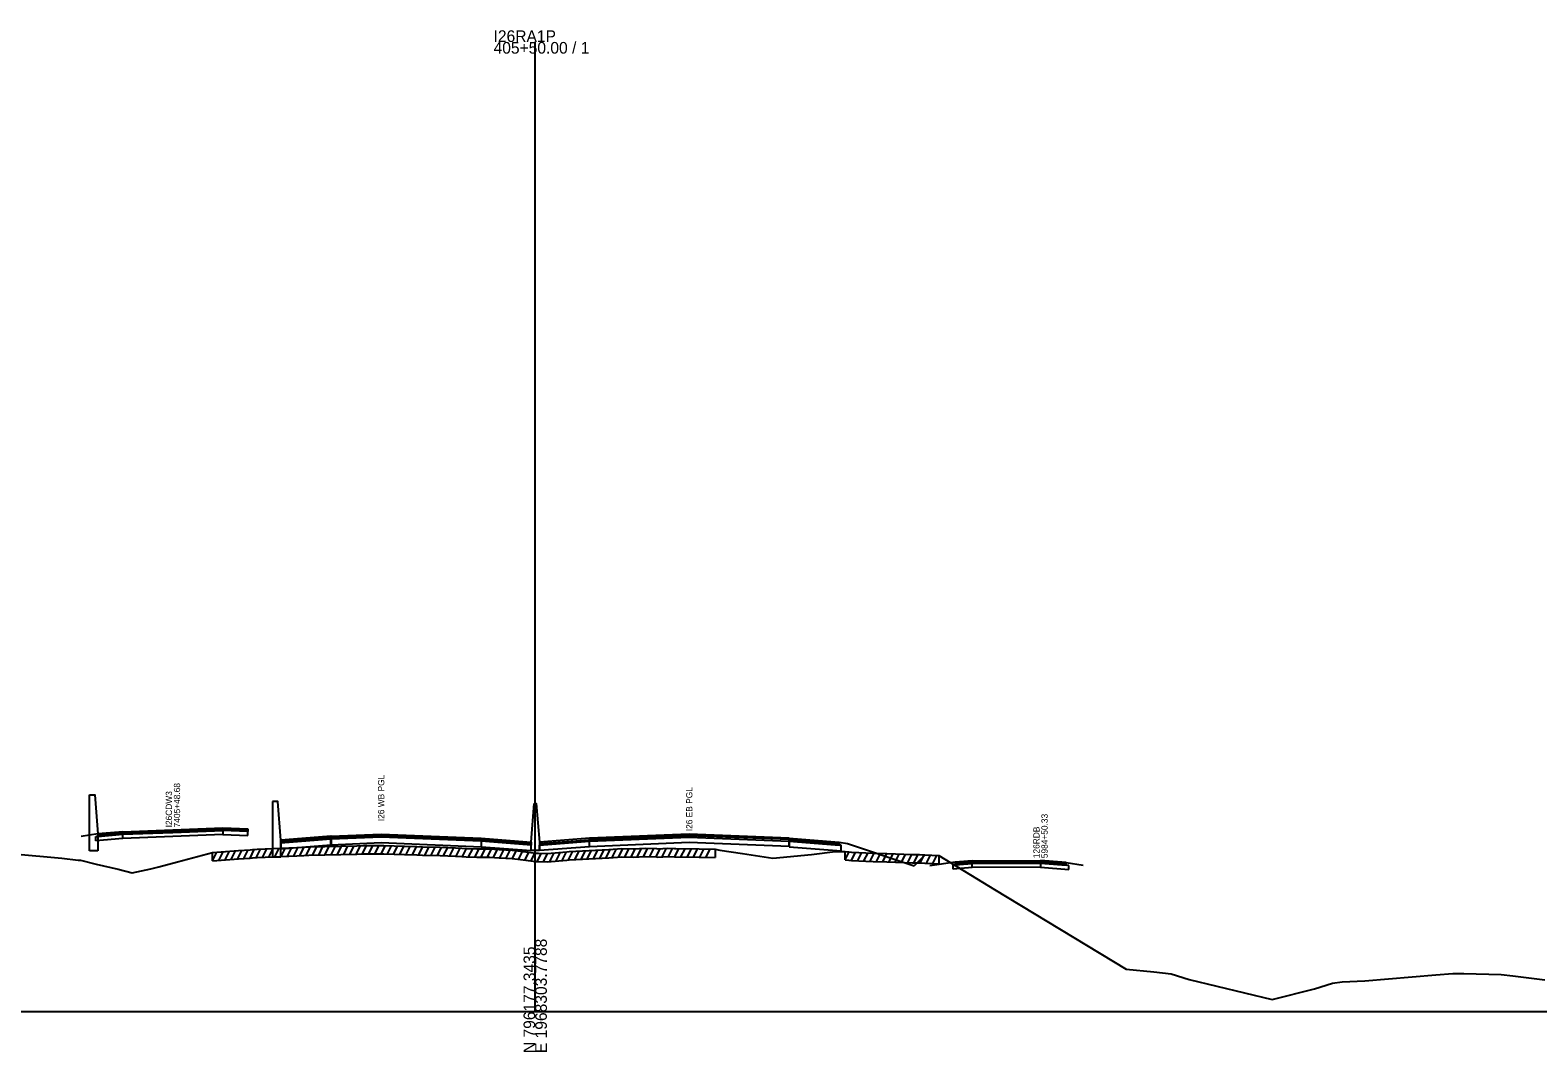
# Model space of a CAD drawing. Extents: x 1017 to 19997, y -1947 to 50737.
# Drawn here: x 16478.7 to 16840.8, y 5490.3 to 5735.7 of the extents above; entities that cross this region are included whole.
import ezdxf

# ---------------------------------------------------------------- set-up
doc = ezdxf.new("R2010")
doc.units = 0
for name, color, linetype in [('RD_GPK_XS_Cell', 7, 'Continuous'), ('RD_XS_Base', 7, 'Continuous'), ('RD_XS_ExGround', 7, 'Continuous'), ('RD_XS_ExPaveRet', 7, 'Continuous'), ('RD_XS_Greenside', 7, 'Continuous'), ('RD_XS_MedBWall', 7, 'Continuous'), ('RD_XS_Pave', 7, 'Continuous'), ('RD_XS_PaveOvlay', 7, 'Continuous'), ('RD_XS_TieSlope', 7, 'Continuous'), ('RD_XS_TX_Notes', 7, 'Continuous')]:
    doc.layers.add(name, color=color, linetype=linetype)

msp = doc.modelspace()

# ---------------------------------------------------------------- linework, layer by layer
at = {"layer": 'RD_GPK_XS_Cell'}
for p, q in [((16600, 5500), (16600, 5732.84)), ((16000, 5500), (16600, 5500)), ((16600, 5500), (17200, 5500))]:
    msp.add_line(p, q, dxfattribs=at)
at = {"layer": 'RD_XS_Base'}
for points in [[(16525, 5543.5), (16525, 5542.5)], [(16531, 5542.25), (16531, 5543.25)], [(16494.5, 5542.02), (16495, 5542.06), (16501, 5542.55)], [(16494.5, 5541.02), (16494.5, 5542.02)], [(16501, 5541.55), (16494.5, 5541.02)], [(16501, 5541.55), (16501, 5542.55)], [(16525, 5542.5), (16513, 5542.02), (16501, 5541.55)], [(16525, 5542.5), (16531, 5542.25)], [(16550.95, 5541.4), (16538.95, 5540.44)], [(16538.95, 5540.44), (16538.95, 5539.1)], [(16538.95, 5539.1), (16550.95, 5540.06)], [(16550.95, 5540.06), (16550.95, 5541.4)], [(16551, 5540.06), (16550.95, 5540.06)], [(16551, 5541.4), (16551, 5540.06)], [(16551, 5540.06), (16563, 5540.55), (16587, 5539.58)], [(16599, 5539.98), (16587, 5540.92)], [(16587, 5540.92), (16587, 5539.58)], [(16587, 5539.58), (16599, 5538.64)], [(16599, 5538.64), (16599, 5539.98)], [(16601, 5538.64), (16601, 5539.98)], [(16613, 5539.58), (16601, 5538.64)], [(16613, 5539.58), (16613, 5540.92)], [(16660.95, 5539.59), (16637, 5540.55), (16613, 5539.58)], [(16660.95, 5539.59), (16660.95, 5540.93)], [(16661, 5539.58), (16660.95, 5539.59)], [(16661, 5540.92), (16661, 5539.58)], [(16673.5, 5539.93), (16673, 5539.97), (16661, 5540.92)], [(16661, 5539.58), (16673.5, 5538.59)], [(16673.5, 5538.59), (16673.5, 5539.93)], [(16700.37, 5535.21), (16700.89, 5535.25), (16704.97, 5535.56)], [(16700.37, 5534.21), (16700.37, 5535.21)], [(16704.97, 5534.56), (16700.37, 5534.21)], [(16704.97, 5534.56), (16704.97, 5535.56)], [(16721.33, 5534.63), (16704.97, 5534.56)], [(16721.33, 5535.63), (16721.33, 5534.63)], [(16728.18, 5535.08), (16727.47, 5535.14), (16721.33, 5535.63)], [(16721.33, 5534.63), (16728.18, 5534.08)], [(16728.18, 5534.08), (16728.18, 5535.08)]]:
    msp.add_lwpolyline(points, dxfattribs=at)
at = {"layer": 'RD_XS_ExGround'}
msp.add_lwpolyline([(16474.76, 5537.9), (16486.29, 5536.81), (16490.21, 5536.38), (16490.77, 5536.31), (16494.57, 5535.38), (16499.84, 5534.15), (16503.21, 5533.29), (16507.73, 5534.28), (16509.62, 5534.78), (16514.11, 5535.98), (16522.51, 5538.2), (16528.71, 5538.63), (16531.56, 5538.83), (16532.09, 5538.87), (16533.21, 5538.95), (16542.75, 5539.41), (16544.4, 5539.5), (16545.62, 5539.52), (16557.16, 5539.81), (16558.77, 5539.83), (16563.64, 5539.88), (16568.64, 5539.69), (16571.59, 5539.59), (16572.91, 5539.56), (16577.21, 5539.48), (16580.84, 5539.3), (16582.4, 5539.22), (16583.39, 5539.16), (16585.96, 5539.03), (16588.77, 5539.08), (16589.09, 5539.08), (16591.31, 5538.93), (16594.48, 5538.72), (16597.12, 5538.39), (16600.12, 5538.01), (16600.76, 5538), (16602.88, 5537.98), (16607.63, 5538.37), (16608.15, 5538.42), (16617.7, 5538.92), (16620.84, 5539.11), (16623.49, 5539.05), (16626.49, 5539.24), (16629.11, 5539.12), (16629.46, 5539.1), (16631.87, 5539.21), (16633.47, 5539.15), (16633.81, 5539.14), (16639.37, 5539.03), (16643.19, 5538.96), (16644.34, 5538.78), (16649.77, 5537.95), (16657.05, 5536.86), (16666.36, 5537.73), (16672.06, 5538.42), (16673.77, 5538.41), (16674.45, 5538.4), (16675.32, 5538.34), (16675.96, 5538.3), (16681.16, 5538.06), (16684.43, 5537.92), (16690.62, 5537.72), (16691.05, 5537.71), (16692.32, 5537.67), (16693.53, 5537.61), (16696.91, 5537.45), (16710.3, 5529.33), (16741.94, 5510.2), (16748.59, 5509.52), (16752.75, 5509.08), (16757.08, 5507.7), (16777.01, 5502.9), (16787.12, 5505.44), (16791.44, 5506.81), (16793.78, 5507.09), (16799.21, 5507.36), (16816.3, 5508.78), (16820.36, 5509.14), (16822.97, 5509.11), (16832, 5508.87), (16834.77, 5508.58), (16842.45, 5507.63)], dxfattribs=at)
at = {"layer": 'RD_XS_ExPaveRet'}
for p, q in [((16546.51, 5537.54), (16547.52, 5539.57)), ((16548.01, 5537.58), (16549.02, 5539.61)), ((16549.51, 5537.62), (16550.52, 5539.64)), ((16551.01, 5537.66), (16552.02, 5539.68)), ((16552.51, 5537.69), (16553.52, 5539.72)), ((16554.01, 5537.73), (16555.02, 5539.75)), ((16555.51, 5537.77), (16556.52, 5539.79)), ((16557.01, 5537.8), (16558.02, 5539.82)), ((16558.51, 5537.83), (16559.52, 5539.84)), ((16560.01, 5537.84), (16561.02, 5539.86)), ((16561.51, 5537.86), (16562.52, 5539.87)), ((16563.01, 5537.88), (16564.01, 5539.87)), ((16564.51, 5537.85), (16565.49, 5539.81)), ((16566.01, 5537.79), (16566.99, 5539.76)), ((16567.51, 5537.74), (16568.49, 5539.7)), ((16569.01, 5537.68), (16569.99, 5539.65)), ((16570.51, 5537.63), (16571.49, 5539.6)), ((16572.01, 5537.58), (16573, 5539.55)), ((16522.51, 5536.2), (16523.55, 5538.27)), ((16522.51, 5536.2), (16522.51, 5538.2)), ((16522.51, 5536.2), (16528.71, 5536.63)), ((16524.01, 5536.3), (16525.05, 5538.37)), ((16525.51, 5536.41), (16526.55, 5538.48)), ((16527.01, 5536.51), (16528.05, 5538.58)), ((16528.51, 5536.62), (16529.55, 5538.69)), ((16528.71, 5536.63), (16531.56, 5536.83)), ((16530.01, 5536.72), (16531.05, 5538.79)), ((16531.51, 5536.82), (16532.55, 5538.9)), ((16531.56, 5536.83), (16532.09, 5536.87)), ((16532.09, 5536.87), (16533.21, 5536.95)), ((16533.01, 5536.94), (16534.04, 5538.99)), ((16533.21, 5536.95), (16542.75, 5537.41)), ((16534.51, 5537.02), (16535.54, 5539.07)), ((16536.01, 5537.09), (16537.04, 5539.14)), ((16537.51, 5537.16), (16538.54, 5539.21)), ((16539.01, 5537.23), (16540.04, 5539.28)), ((16540.51, 5537.31), (16541.54, 5539.36)), ((16542.01, 5537.38), (16543.04, 5539.43)), ((16542.75, 5537.41), (16544.4, 5537.5)), ((16543.51, 5537.45), (16544.54, 5539.5)), ((16544.4, 5537.5), (16545.62, 5537.52)), ((16545.01, 5537.51), (16546.02, 5539.53)), ((16545.62, 5537.52), (16557.16, 5537.81)), ((16557.16, 5537.81), (16558.77, 5537.83)), ((16558.77, 5537.83), (16563.64, 5537.88)), ((16563.64, 5537.88), (16568.64, 5537.69)), ((16568.64, 5537.69), (16571.59, 5537.59)), ((16571.59, 5537.59), (16572.91, 5537.56)), ((16572.91, 5537.56), (16577.21, 5537.48)), ((16573.51, 5537.54), (16574.5, 5539.53)), ((16575.01, 5537.52), (16576, 5539.5)), ((16576.51, 5537.49), (16577.5, 5539.46)), ((16577.21, 5537.48), (16580.84, 5537.3)), ((16578.01, 5537.44), (16578.99, 5539.39)), ((16579.51, 5537.36), (16580.49, 5539.31)), ((16580.84, 5537.3), (16582.4, 5537.22)), ((16581.01, 5537.29), (16581.99, 5539.24)), ((16582.4, 5537.22), (16583.39, 5537.16)), ((16582.51, 5537.21), (16583.48, 5539.15)), ((16583.39, 5537.16), (16585.96, 5537.03)), ((16584.01, 5537.13), (16584.99, 5539.08)), ((16585.51, 5537.05), (16586.51, 5539.04)), ((16585.96, 5537.03), (16588.77, 5537.08)), ((16587.01, 5537.05), (16588.02, 5539.07)), ((16588.51, 5537.08), (16589.5, 5539.05)), ((16588.77, 5537.08), (16589.09, 5537.08)), ((16589.09, 5537.08), (16591.31, 5536.93)), ((16590.01, 5537.02), (16590.98, 5538.96)), ((16591.31, 5536.93), (16594.48, 5536.72)), ((16591.51, 5536.92), (16592.48, 5538.85)), ((16593.01, 5536.82), (16593.98, 5538.75)), ((16594.48, 5536.72), (16597.12, 5536.39)), ((16594.51, 5536.71), (16595.45, 5538.6)), ((16596.01, 5536.53), (16596.95, 5538.41)), ((16597.12, 5536.39), (16600.12, 5536.01)), ((16597.51, 5536.34), (16598.45, 5538.22)), ((16599.01, 5536.15), (16599.95, 5538.04)), ((16600.12, 5536.01), (16600.76, 5536)), ((16600.51, 5536.01), (16601.51, 5538)), ((16600.76, 5536), (16602.88, 5535.98)), ((16602.01, 5535.99), (16603.01, 5537.99)), ((16602.88, 5535.98), (16607.63, 5536.37)), ((16603.51, 5536.03), (16604.55, 5538.12)), ((16605.01, 5536.16), (16606.05, 5538.24)), ((16606.51, 5536.28), (16607.55, 5538.37)), ((16607.63, 5536.37), (16608.15, 5536.42)), ((16608.01, 5536.41), (16609.04, 5538.47)), ((16608.15, 5536.42), (16617.7, 5536.92)), ((16609.51, 5536.49), (16610.54, 5538.54)), ((16611.01, 5536.57), (16612.04, 5538.62)), ((16612.51, 5536.65), (16613.54, 5538.7)), ((16614.01, 5536.73), (16615.04, 5538.78)), ((16615.51, 5536.81), (16616.54, 5538.86)), ((16617.01, 5536.88), (16618.04, 5538.94)), ((16617.7, 5536.92), (16620.84, 5537.11)), ((16618.51, 5536.97), (16619.54, 5539.03)), ((16620.01, 5537.06), (16621.03, 5539.1)), ((16620.84, 5537.11), (16623.49, 5537.05)), ((16621.51, 5537.09), (16622.5, 5539.07)), ((16623.01, 5537.06), (16624.02, 5539.09)), ((16623.49, 5537.05), (16626.49, 5537.24)), ((16624.51, 5537.12), (16625.55, 5539.18)), ((16626.01, 5537.21), (16627.01, 5539.22)), ((16626.49, 5537.24), (16629.11, 5537.12)), ((16627.51, 5537.2), (16628.49, 5539.15)), ((16629.01, 5537.12), (16630.01, 5539.13)), ((16629.11, 5537.12), (16629.46, 5537.1)), ((16629.46, 5537.1), (16631.87, 5537.21)), ((16630.51, 5537.15), (16631.53, 5539.19)), ((16631.87, 5537.21), (16633.47, 5537.15)), ((16632.01, 5537.2), (16633, 5539.17)), ((16633.47, 5537.15), (16633.81, 5537.14)), ((16633.51, 5537.15), (16634.5, 5539.13)), ((16633.81, 5537.14), (16639.37, 5537.03)), ((16635.01, 5537.12), (16636, 5539.1)), ((16636.51, 5537.09), (16637.5, 5539.07)), ((16638.01, 5537.06), (16639, 5539.04)), ((16639.37, 5537.03), (16643.19, 5536.96)), ((16639.51, 5537.03), (16640.5, 5539.01)), ((16641.01, 5537), (16642, 5538.98)), ((16643.19, 5538.96), (16643.19, 5536.96)), ((16674.45, 5536.4), (16674.45, 5538.4)), ((16674.45, 5536.4), (16675.42, 5538.34)), ((16674.45, 5536.4), (16675.32, 5536.34)), ((16675.32, 5536.34), (16675.96, 5536.3)), ((16675.95, 5536.3), (16676.93, 5538.26)), ((16675.96, 5536.3), (16681.16, 5536.06)), ((16677.45, 5536.23), (16678.43, 5538.19)), ((16678.95, 5536.16), (16679.93, 5538.12)), ((16680.45, 5536.1), (16681.43, 5538.05)), ((16681.16, 5536.06), (16684.43, 5535.92)), ((16681.95, 5536.03), (16682.93, 5537.98)), ((16683.45, 5535.96), (16684.43, 5537.92)), ((16684.95, 5535.9), (16685.93, 5537.87)), ((16686.45, 5535.85), (16687.43, 5537.82)), ((16687.95, 5535.8), (16688.93, 5537.77)), ((16689.45, 5535.76), (16690.43, 5537.73)), ((16690.95, 5535.71), (16691.93, 5537.68)), ((16692.45, 5535.66), (16693.43, 5537.62)), ((16693.95, 5535.59), (16694.93, 5537.55)), ((16695.45, 5535.52), (16696.43, 5537.47)), ((16696.91, 5537.45), (16696.91, 5535.45)), ((16684.43, 5535.92), (16690.62, 5535.72)), ((16690.62, 5535.72), (16691.05, 5535.71)), ((16691.05, 5535.71), (16692.32, 5535.67)), ((16692.32, 5535.67), (16693.53, 5535.61)), ((16693.53, 5535.61), (16696.91, 5535.45))]:
    msp.add_line(p, q, dxfattribs=at)
at = {"layer": 'RD_XS_Greenside'}
for points in [[(16495, 5542.7), (16491, 5542.06)], [(16673, 5540.64), (16675, 5540.31)], [(16675, 5540.31), (16691, 5534.97)], [(16700.89, 5535.88), (16694.75, 5534.95)], [(16727.47, 5535.77), (16731.56, 5535.13)]]:
    msp.add_lwpolyline(points, dxfattribs=at)
at = {"layer": 'RD_XS_MedBWall'}
for points in [[(16493, 5538.56), (16493, 5552.04)], [(16493, 5552.04), (16494.25, 5552.04), (16495, 5542.7)], [(16538.95, 5541.12), (16538.2, 5550.46), (16536.95, 5550.46)], [(16536.95, 5550.46), (16536.95, 5537.12)], [(16599, 5540.64), (16599.75, 5549.98)], [(16599.75, 5549.98), (16600.25, 5549.98), (16601, 5540.64)], [(16495, 5542.7), (16495, 5538.56)], [(16538.95, 5537.12), (16538.95, 5541.12)], [(16599, 5538.64), (16599, 5539.98), (16599, 5540.64)], [(16601, 5540.64), (16601, 5539.98), (16601, 5538.64)], [(16495, 5538.56), (16493, 5538.56)], [(16536.95, 5537.12), (16538.95, 5537.12)], [(16601, 5538.64), (16599, 5538.64)]]:
    msp.add_lwpolyline(points, dxfattribs=at)
at = {"layer": 'RD_XS_Pave'}
for points in [[(16525, 5543.82), (16513, 5543.34), (16501, 5542.86)], [(16501, 5542.55), (16513, 5543.02), (16525, 5543.5)], [(16525, 5543.5), (16525, 5543.82)], [(16525, 5543.82), (16531, 5543.58)], [(16531, 5543.25), (16525, 5543.5)], [(16531, 5543.58), (16531, 5543.25)], [(16495, 5542.38), (16501, 5542.86)], [(16501, 5542.55), (16495, 5542.06)], [(16495, 5542.06), (16495, 5542.38)], [(16501, 5542.86), (16501, 5542.55)], [(16550.95, 5541.74), (16538.95, 5540.78)], [(16538.95, 5540.78), (16538.95, 5540.44)], [(16550.95, 5541.74), (16551, 5541.74)], [(16550.95, 5541.4), (16550.95, 5541.74)], [(16551, 5541.4), (16550.95, 5541.4)], [(16587, 5540.92), (16563, 5541.89), (16551, 5541.4)], [(16551, 5541.74), (16551, 5541.4)], [(16587, 5541.26), (16587, 5540.92)], [(16587, 5541.26), (16599, 5540.32)], [(16599, 5540.32), (16599, 5539.98)], [(16601, 5539.98), (16613, 5540.92)], [(16601, 5540.32), (16601, 5539.98)], [(16660.95, 5541.27), (16637, 5542.22), (16613, 5541.26)], [(16613, 5540.92), (16637, 5541.89), (16660.95, 5540.93)], [(16613, 5541.26), (16613, 5540.92)], [(16660.95, 5541.27), (16661, 5541.26)], [(16660.95, 5540.93), (16660.95, 5541.27)], [(16661, 5540.92), (16660.95, 5540.93)], [(16661, 5541.26), (16661, 5540.92)], [(16661, 5540.92), (16673, 5539.97)], [(16673, 5539.97), (16673, 5540.3)], [(16721.33, 5535.95), (16704.97, 5535.87)], [(16721.33, 5535.63), (16721.33, 5535.95)], [(16727.47, 5535.46), (16721.33, 5535.95)], [(16704.97, 5535.87), (16700.89, 5535.57)], [(16700.89, 5535.57), (16700.89, 5535.25)], [(16700.89, 5535.25), (16704.97, 5535.56)], [(16704.97, 5535.87), (16704.97, 5535.56)], [(16704.97, 5535.56), (16721.33, 5535.63)], [(16721.33, 5535.63), (16727.47, 5535.14)], [(16727.47, 5535.14), (16727.47, 5535.46)]]:
    msp.add_lwpolyline(points, dxfattribs=at)
at = {"layer": 'RD_XS_PaveOvlay'}
for points in [[(16501, 5543.18), (16495, 5542.7)], [(16501, 5543.18), (16513, 5543.66), (16525, 5544.14)], [(16501, 5542.86), (16501, 5543.18)], [(16525, 5544.14), (16525, 5543.82)], [(16525, 5544.14), (16531, 5543.9)], [(16531, 5543.9), (16531, 5543.58)], [(16495, 5542.7), (16495, 5542.38)], [(16550.95, 5542.08), (16538.95, 5541.12)], [(16538.95, 5541.12), (16538.95, 5540.78)], [(16551, 5542.08), (16550.95, 5542.08)], [(16550.95, 5542.08), (16550.95, 5541.74)], [(16551, 5542.08), (16563, 5542.56), (16587, 5541.6)], [(16587, 5541.26), (16563, 5542.22), (16551, 5541.74)], [(16551, 5541.74), (16551, 5542.08)], [(16587, 5541.6), (16587, 5541.26)], [(16587, 5541.6), (16599, 5540.64)], [(16599, 5540.64), (16599, 5540.32)], [(16613, 5541.6), (16601, 5540.64)], [(16601, 5540.32), (16613, 5541.26)], [(16601, 5540.64), (16601, 5540.32)], [(16660.95, 5541.6), (16637, 5542.56), (16613, 5541.6)], [(16613, 5541.26), (16613, 5541.6)], [(16660.95, 5541.6), (16661, 5541.6)], [(16660.95, 5541.27), (16660.95, 5541.6)], [(16661, 5541.6), (16673, 5540.64)], [(16661, 5541.26), (16661, 5541.6)], [(16673, 5540.3), (16661, 5541.26)], [(16673, 5540.64), (16673, 5540.3)], [(16704.97, 5536.19), (16700.89, 5535.88)], [(16704.97, 5536.19), (16721.33, 5536.26)], [(16704.97, 5535.87), (16704.97, 5536.19)], [(16721.33, 5536.26), (16721.33, 5535.95)], [(16727.47, 5535.77), (16721.33, 5536.26)], [(16700.89, 5535.88), (16700.89, 5535.57)], [(16727.47, 5535.46), (16727.47, 5535.77)]]:
    msp.add_lwpolyline(points, dxfattribs=at)
at = {"layer": 'RD_XS_TieSlope'}
msp.add_lwpolyline([(16691, 5534.97), (16693.64, 5537.61)], dxfattribs=at)

# ---------------------------------------------------------------- texts
at = {"layer": 'RD_GPK_XS_Cell'}
for s, p in [('I26RA1P', (16590, 5732.84)), ('405+50.00 / 1', (16590, 5730.04))]:
    msp.add_text(s, height=2.8, dxfattribs=at).set_placement(p)
for s, p in [('N 796177.3435', (16600, 5490)), ('E 1968303.7788', (16602.8, 5490))]:
    msp.add_text(s, height=2.8, rotation=90, dxfattribs=at).set_placement(p)
at = {"layer": 'RD_XS_TX_Notes'}
for s, p in [(' 7405+48.68', (16514.73, 5543.66)), ('I26 WB PGL', (16563.75, 5545.71)), (' I26CDW3', (16512.77, 5543.66)), ('I26 EB PGL', (16637.75, 5543.29)), (' 5984+50.33', (16723.06, 5536.26)), (' 126RDB', (16721.11, 5536.26))]:
    msp.add_text(s, height=1.5, rotation=90, dxfattribs=at).set_placement(p)

doc.saveas('drawing.dxf')
